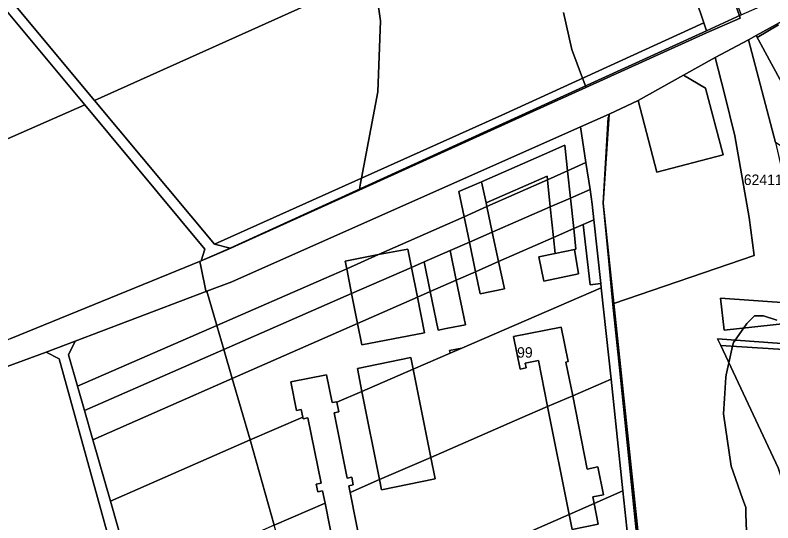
# Model space of a CAD drawing. Extents: x -522079 to -518833, y -1142400 to -1139961.
# Drawn here: x -520985.3 to -520623.1, y -1141048.7 to -1140806 of the extents above; entities that cross this region are included whole.
import ezdxf

# ---------------------------------------------------------------- set-up
doc = ezdxf.new("R2010")
doc.units = 0
for name, color, linetype in [('95560013', 7, 'Continuous'), ('95590013', 7, 'Continuous'), ('95600013', 7, 'Continuous'), ('95610013', 7, 'Continuous'), ('95640013', 7, 'Continuous'), ('95660013', 7, 'Continuous')]:
    doc.layers.add(name, color=color, linetype=linetype)

msp = doc.modelspace()

# ---------------------------------------------------------------- linework, layer by layer
at = {"layer": '95560013'}
for points in [[(-521187.8, -1140573.75), (-521174.07, -1140567.72), (-521175.11, -1140573.76), (-521134.28, -1140622.71), (-521036.95, -1140739.4), (-520947.33, -1140846.85), (-520890.08, -1140915.49), (-520882.47, -1140917.37), (-520896.33, -1140923.45), (-520894.6, -1140917.89), (-520952.05, -1140848.96), (-521041.47, -1140741.65), (-521139.09, -1140624.65), (-521179.71, -1140575.8)], [(-521036.95, -1140739.4), (-520897.82, -1140676.39), (-520765.71, -1140616.57), (-520757.18, -1140627.06), (-520745.42, -1140642.26), (-520733.42, -1140657.97), (-520724.12, -1140671.61), (-520771, -1140692.05), (-520722.34, -1140745.4), (-520809.38, -1140784.65), (-520947.33, -1140846.85)], [(-520752.69, -1140853.85), (-520890.08, -1140915.49), (-520947.33, -1140846.85), (-520809.38, -1140784.65), (-520722.34, -1140745.4), (-520689.02, -1140730.38), (-520682.43, -1140743.84), (-520674.16, -1140762.17), (-520669.15, -1140773.31), (-520664.94, -1140785.33), (-520657.77, -1140804.5), (-520656.02, -1140809.72)], [(-521234.98, -1140825.42), (-521164.66, -1140794.98), (-521041.47, -1140741.65), (-520952.05, -1140848.96), (-521133.42, -1140928.49), (-521179.82, -1140867.68), (-521217.11, -1140828.01)], [(-521133.42, -1140928.49), (-520952.05, -1140848.96), (-520894.6, -1140917.89), (-520896.33, -1140923.45), (-520987.34, -1140960.66), (-521077.97, -1140999.02), (-521081.12, -1140996.97)], [(-520893.74, -1140937.98), (-520888.93, -1140954.41), (-520955.5, -1140983.4), (-520959.78, -1140968.46), (-520956.56, -1140961.79)], [(-520888.93, -1140954.41), (-520885.58, -1140965.84), (-520952.2, -1140994.93), (-520955.5, -1140983.4)], [(-520948.18, -1141008.97), (-520939.75, -1141038.42), (-520928.14, -1141079.25), (-520914.59, -1141129.89), (-520890.98, -1141218.17), (-520890.16, -1141218.54), (-520895.96, -1141221.04), (-520895.4, -1141219.71), (-520927.66, -1141102.94), (-520964.29, -1140970.32), (-520970.5, -1140967.09), (-520956.56, -1140961.79), (-520959.78, -1140968.46), (-520955.5, -1140983.4), (-520952.2, -1140994.93)], [(-520895.4, -1141219.71), (-520895.96, -1141221.04), (-521038.45, -1141284.46), (-521072.62, -1141164.33), (-521112.83, -1141022.98), (-521082.18, -1141009.47), (-521026.59, -1140987.63), (-520970.5, -1140967.09), (-520964.29, -1140970.32), (-520927.66, -1141102.94)], [(-520885.58, -1140965.84), (-520881.52, -1140979.72), (-520948.18, -1141008.97), (-520952.2, -1140994.93)], [(-520881.52, -1140979.72), (-520872.93, -1141009.05), (-520939.75, -1141038.42), (-520948.18, -1141008.97)], [(-520861.45, -1141049.84), (-520928.14, -1141079.25), (-520939.75, -1141038.42), (-520872.93, -1141009.05)]]:
    msp.add_lwpolyline(points, close=True, dxfattribs=at)
at = {"layer": '95590013'}
for points in [[(-520607.5, -1140876.29), (-520621.9, -1140866.86), (-520634.79, -1140817.77), (-520631.12, -1140815.76), (-520626.71, -1140823.74), (-520615.7, -1140843.89), (-520602.23, -1140836.31)], [(-520655.25, -1140840.87), (-520646.86, -1140872.86), (-520678.48, -1140881.15), (-520687.49, -1140846.81), (-520665.74, -1140834.79)], [(-520649.51, -1140960.76), (-520594.75, -1140964.79), (-520599.73, -1140986.18), (-520599.81, -1140983.06), (-520599.94, -1140978.24), (-520600.24, -1140966.98), (-520648.03, -1140963.9)], [(-520620.51, -1141022.34), (-520648.03, -1140963.9), (-520600.24, -1140966.98), (-520604.67, -1140967.12), (-520604.41, -1140978.31), (-520604.3, -1140983.07), (-520599.81, -1140983.06), (-520599.73, -1140986.18), (-520599.09, -1141003), (-520600.97, -1141003.07), (-520601.06, -1141001.34), (-520601.36, -1141001.34), (-520602.52, -1141000.7), (-520603.99, -1141000.76), (-520605.04, -1141001.54), (-520605.37, -1141001.56), (-520605.29, -1141003.25), (-520607.09, -1141003.32), (-520615.08, -1141003.61), (-520614.42, -1141021.92), (-520598.37, -1141020.83), (-520596.21, -1141046.3), (-520612.04, -1141047.58)]]:
    msp.add_lwpolyline(points, close=True, dxfattribs=at)
at = {"layer": '95600013'}
msp.add_lwpolyline([(-520699.09, -1140943.92), (-520704.17, -1140895.93), (-520701.37, -1140853.35), (-520687.49, -1140846.81), (-520678.48, -1140881.15), (-520646.86, -1140872.86), (-520655.25, -1140840.87), (-520665.74, -1140834.79), (-520650.7, -1140826.31), (-520646.19, -1140843.58), (-520641.23, -1140863.72), (-520634.37, -1140902.81), (-520632.04, -1140920.85)], close=True, dxfattribs=at)
at = {"layer": '95610013'}
for points in [[(-520679.92, -1141124.76), (-520699.09, -1140943.92), (-520632.04, -1140920.85), (-520634.37, -1140902.81), (-520641.23, -1140863.72), (-520646.19, -1140843.58), (-520650.7, -1140826.31), (-520634.79, -1140817.77), (-520621.9, -1140866.86), (-520618.56, -1140880.81), (-520614.37, -1140907.34), (-520612.5, -1140933.48), (-520590.36, -1140946.34), (-520594.75, -1140964.79), (-520649.51, -1140960.76), (-520648.03, -1140963.9), (-520620.51, -1141022.34), (-520612.04, -1141047.58), (-520596.21, -1141046.3), (-520599.33, -1141085.41), (-520603.47, -1141094.45), (-520605.48, -1141096), (-520676.95, -1141126.77)], [(-520614.33, -1140943.77), (-520648.15, -1140941.33), (-520646.42, -1140956.53), (-520615.62, -1140953.33)], [(-520615.62, -1140953.33), (-520646.42, -1140956.53), (-520648.15, -1140941.33), (-520614.33, -1140943.77)]]:
    msp.add_lwpolyline(points, close=True, dxfattribs=at)
at = {"layer": '95640013'}
for points in [[(-520657.77, -1140804.5), (-520664.94, -1140785.33), (-520669.15, -1140773.31), (-520674.16, -1140762.17), (-520682.43, -1140743.84), (-520689.02, -1140730.38), (-520701.8, -1140708.2), (-520711.88, -1140691.39), (-520722.11, -1140674.56), (-520715.02, -1140671.04), (-520673.31, -1140722.41), (-520669.12, -1140730.36), (-520666.3, -1140735.71), (-520657.82, -1140755.57), (-520652.69, -1140766.32), (-520641.11, -1140798.37), (-520638.22, -1140805.93), (-520654.73, -1140813.47), (-520656.02, -1140809.72)], [(-520615.7, -1140843.89), (-520626.71, -1140823.74), (-520631.12, -1140815.76), (-520613.67, -1140806.13), (-520609.23, -1140813.72), (-520607.3, -1140817.32), (-520601.28, -1140828.55), (-520598.3, -1140834.1), (-520602.23, -1140836.31)], [(-520654.73, -1140813.47), (-520708.35, -1140837.86), (-520882.47, -1140917.37), (-520890.08, -1140915.49), (-520752.69, -1140853.85), (-520656.02, -1140809.72)], [(-520708.6, -1140903.84), (-520709.39, -1140896.44), (-520710.48, -1140889.38), (-520712.47, -1140876.54), (-520715.12, -1140859.45), (-520701.37, -1140853.35), (-520704.17, -1140895.93), (-520699.09, -1140943.92), (-520679.92, -1141124.76), (-520676.95, -1141126.77), (-520686.99, -1141131.09), (-520684.73, -1141127.15), (-520694.75, -1141033.39), (-520700.46, -1140980.02), (-520705.13, -1140936.35), (-520705.35, -1140934.26)], [(-520893.74, -1140937.98), (-520881.74, -1140933.43), (-520715.12, -1140859.45), (-520712.47, -1140876.54), (-520721.23, -1140880.43), (-520722.52, -1140868.25), (-520732.19, -1140872.47), (-520762.38, -1140885.66), (-520773.2, -1140890.38), (-520770.69, -1140902.38), (-520811.57, -1140920.51), (-520827.55, -1140923.57), (-520826.81, -1140927.27), (-520837.76, -1140932.13), (-520888.93, -1140954.41)], [(-520731.06, -1140883.01), (-520760.22, -1140895.75), (-520762.38, -1140885.66), (-520732.19, -1140872.47), (-520722.52, -1140868.25), (-520721.23, -1140880.43), (-520730.88, -1140884.71)], [(-520712.47, -1140876.54), (-520710.48, -1140889.38), (-520719.85, -1140893.47), (-520721.23, -1140880.43)], [(-520729.49, -1140897.68), (-520730.88, -1140884.71), (-520721.23, -1140880.43), (-520719.85, -1140893.47)], [(-520731.06, -1140883.01), (-520730.88, -1140884.71), (-520759.83, -1140897.56), (-520760.22, -1140895.75)], [(-520759.83, -1140897.56), (-520770.69, -1140902.38), (-520773.2, -1140890.38), (-520762.38, -1140885.66), (-520760.22, -1140895.75)], [(-520730.88, -1140884.71), (-520729.49, -1140897.68), (-520757.2, -1140909.78), (-520759.83, -1140897.56)], [(-520708.6, -1140903.84), (-520713.85, -1140906.14), (-520718.3, -1140908.09), (-520719.85, -1140893.47), (-520710.48, -1140889.38), (-520709.39, -1140896.44)], [(-520718.3, -1140908.09), (-520727.92, -1140912.31), (-520729.49, -1140897.68), (-520719.85, -1140893.47)], [(-520768.14, -1140914.56), (-520770.69, -1140902.38), (-520759.83, -1140897.56), (-520757.2, -1140909.78)], [(-520757.2, -1140909.78), (-520729.49, -1140897.68), (-520727.92, -1140912.31), (-520754.18, -1140923.84)], [(-520789.8, -1140924.02), (-520795.87, -1140926.67), (-520797.62, -1140917.84), (-520811.57, -1140920.51), (-520770.69, -1140902.38), (-520768.14, -1140914.56), (-520777.38, -1140918.59)], [(-520771.7, -1140965.19), (-520777.69, -1140966.37), (-520777.43, -1140967.67), (-520795, -1140975.29), (-520796.11, -1140969.72), (-520821.72, -1140974.86), (-520819.52, -1140985.91), (-520831.48, -1140991.09), (-520831.54, -1140990.79), (-520833.81, -1140991.24), (-520836.46, -1140978.01), (-520853.53, -1140981.34), (-520850.82, -1140994.93), (-520848.51, -1140994.47), (-520847.77, -1140998.15), (-520872.93, -1141009.05), (-520881.52, -1140979.72), (-520821.62, -1140953.44), (-520819.6, -1140963.59), (-520789.67, -1140957.86), (-520793.04, -1140940.9), (-520786.9, -1140938.2), (-520783.12, -1140956.66), (-520778.49, -1140955.67), (-520770.1, -1140954.09), (-520774.48, -1140932.75), (-520765.19, -1140928.67), (-520762.97, -1140939.31), (-520751.37, -1140936.93), (-520754.18, -1140923.84), (-520727.92, -1140912.31), (-520727.11, -1140919.89), (-520735.04, -1140921.52), (-520732.57, -1140933.11), (-520716.01, -1140929.71), (-520717.99, -1140918.02), (-520717.26, -1140917.87), (-520718.3, -1140908.09), (-520713.85, -1140906.14), (-520710.35, -1140934.87), (-520705.35, -1140934.26), (-520705.13, -1140936.35)], [(-520705.35, -1140934.26), (-520710.35, -1140934.87), (-520713.85, -1140906.14), (-520708.6, -1140903.84)], [(-520768.14, -1140914.56), (-520757.2, -1140909.78), (-520754.18, -1140923.84), (-520765.19, -1140928.67)], [(-520718.3, -1140908.09), (-520717.26, -1140917.87), (-520717.99, -1140918.02), (-520727.11, -1140919.89), (-520727.92, -1140912.31)], [(-520765.19, -1140928.67), (-520774.48, -1140932.75), (-520777.38, -1140918.59), (-520768.14, -1140914.56)], [(-520827.55, -1140923.57), (-520811.57, -1140920.51), (-520826.81, -1140927.27)], [(-520826.81, -1140927.27), (-520811.57, -1140920.51), (-520797.62, -1140917.84), (-520795.87, -1140926.67), (-520824.45, -1140939.15)], [(-520777.38, -1140918.59), (-520774.48, -1140932.75), (-520786.9, -1140938.2), (-520789.8, -1140924.02)], [(-520735.04, -1140921.52), (-520727.11, -1140919.89), (-520717.99, -1140918.02), (-520716.01, -1140929.71), (-520732.57, -1140933.11)], [(-520786.9, -1140938.2), (-520793.04, -1140940.9), (-520795.87, -1140926.67), (-520789.8, -1140924.02)], [(-520754.18, -1140923.84), (-520751.37, -1140936.93), (-520762.97, -1140939.31), (-520765.19, -1140928.67)], [(-520837.76, -1140932.13), (-520826.81, -1140927.27), (-520824.45, -1140939.15), (-520885.58, -1140965.84), (-520888.93, -1140954.41)], [(-520793.04, -1140940.9), (-520821.62, -1140953.44), (-520824.45, -1140939.15), (-520795.87, -1140926.67)], [(-520774.48, -1140932.75), (-520770.1, -1140954.09), (-520778.49, -1140955.67), (-520783.12, -1140956.66), (-520786.9, -1140938.2)], [(-520718.75, -1140987.95), (-520721.98, -1140971.84), (-520720.99, -1140971.64), (-520724.28, -1140955.17), (-520747.03, -1140959.63), (-520743.94, -1140975.23), (-520741.04, -1140974.65), (-520741.49, -1140972.39), (-520735.16, -1140971.13), (-520730.77, -1140993.16), (-520743.97, -1140998.9), (-520786.64, -1141017.41), (-520795, -1140975.29), (-520777.43, -1140967.67), (-520771.7, -1140965.19), (-520705.13, -1140936.35), (-520700.46, -1140980.02)], [(-520824.45, -1140939.15), (-520821.62, -1140953.44), (-520881.52, -1140979.72), (-520885.58, -1140965.84)], [(-520789.67, -1140957.86), (-520819.6, -1140963.59), (-520821.62, -1140953.44), (-520793.04, -1140940.9)], [(-520718.75, -1140987.95), (-520730.77, -1140993.16), (-520735.16, -1140971.13), (-520741.49, -1140972.39), (-520741.04, -1140974.65), (-520743.94, -1140975.23), (-520747.03, -1140959.63), (-520724.28, -1140955.17), (-520720.99, -1140971.64), (-520721.98, -1140971.84)], [(-520777.43, -1140967.67), (-520777.69, -1140966.37), (-520771.7, -1140965.19)], [(-520796.11, -1140969.72), (-520795, -1140975.29), (-520819.52, -1140985.91), (-520821.72, -1140974.86)], [(-520811.14, -1141028.03), (-520819.52, -1140985.91), (-520795, -1140975.29), (-520786.64, -1141017.41)], [(-520704.05, -1141035.32), (-520706.71, -1141021.99), (-520711.86, -1141023.01), (-520718.75, -1140987.95), (-520700.46, -1140980.02), (-520694.75, -1141033.39), (-520708.57, -1141039.45), (-520709.19, -1141036.35)], [(-520811.14, -1141028.03), (-520825.24, -1141034.14), (-520825.88, -1141030.94), (-520823.65, -1141030.49), (-520824.37, -1141026.86), (-520826.6, -1141027.31), (-520832.85, -1140996.06), (-520830.61, -1140995.62), (-520831.48, -1140991.09), (-520819.52, -1140985.91)], [(-520704.05, -1141035.32), (-520709.19, -1141036.35), (-520708.57, -1141039.45), (-520720.5, -1141044.69), (-520730.77, -1140993.16), (-520718.75, -1140987.95), (-520711.86, -1141023.01), (-520706.71, -1141021.99)], [(-520847.24, -1141100.33), (-520861.45, -1141049.84), (-520837.18, -1141039.32), (-520830.7, -1141071.68), (-520832.98, -1141072.14), (-520832.28, -1141075.7), (-520829.99, -1141075.25), (-520829.01, -1141080.15), (-520816.54, -1141077.66), (-520825.24, -1141034.14), (-520811.14, -1141028.03), (-520810.16, -1141032.94), (-520784.59, -1141027.7), (-520786.64, -1141017.41), (-520743.97, -1140998.9), (-520730.77, -1140993.16), (-520720.5, -1141044.69)], [(-520847.61, -1140998.97), (-520845.35, -1140998.52), (-520839.1, -1141029.76), (-520841.35, -1141030.21), (-520840.62, -1141033.83), (-520838.37, -1141033.38), (-520837.18, -1141039.32), (-520861.45, -1141049.84), (-520872.93, -1141009.05), (-520847.77, -1140998.15)], [(-520786.64, -1141017.41), (-520784.59, -1141027.7), (-520810.16, -1141032.94), (-520811.14, -1141028.03)], [(-520727.16, -1141148.38), (-520733.88, -1141082.24), (-520846.14, -1141104.23), (-520847.24, -1141100.33), (-520720.5, -1141044.69), (-520719.07, -1141051.88), (-520706.59, -1141049.39), (-520708.57, -1141039.45), (-520694.75, -1141033.39), (-520684.73, -1141127.15), (-520686.99, -1141131.09)], [(-520706.59, -1141049.39), (-520719.07, -1141051.88), (-520720.5, -1141044.69), (-520708.57, -1141039.45)]]:
    msp.add_lwpolyline(points, close=True, dxfattribs=at)
for points in [[(-520987.34, -1140960.66), (-520896.33, -1140923.45), (-520882.47, -1140917.37), (-520708.35, -1140837.86), (-520654.73, -1140813.47), (-520638.22, -1140805.93), (-520618.93, -1140797.21)], [(-520613.67, -1140806.13), (-520631.12, -1140815.76), (-520634.79, -1140817.77), (-520650.7, -1140826.31), (-520665.74, -1140834.79), (-520687.49, -1140846.81), (-520701.37, -1140853.35), (-520715.12, -1140859.45), (-520881.74, -1140933.43), (-520893.74, -1140937.98), (-520956.56, -1140961.79), (-520970.5, -1140967.09), (-521026.59, -1140987.63)], [(-520830.7, -1141071.68), (-520837.18, -1141039.32), (-520838.37, -1141033.38), (-520840.62, -1141033.83), (-520841.35, -1141030.21), (-520839.1, -1141029.76), (-520845.35, -1140998.52), (-520847.61, -1140998.97), (-520847.77, -1140998.15), (-520848.51, -1140994.47), (-520850.82, -1140994.93), (-520853.53, -1140981.34), (-520836.46, -1140978.01), (-520833.81, -1140991.24), (-520831.54, -1140990.79), (-520831.48, -1140991.09), (-520830.61, -1140995.62), (-520832.85, -1140996.06), (-520826.6, -1141027.31), (-520824.37, -1141026.86), (-520823.65, -1141030.49), (-520825.88, -1141030.94), (-520825.24, -1141034.14), (-520816.54, -1141077.66)]]:
    msp.add_lwpolyline(points, dxfattribs=at)
at = {"layer": '95660013'}
for points in [[(-520861.45, -1141049.84), (-520872.93, -1141009.05), (-520881.52, -1140979.72), (-520885.58, -1140965.84), (-520888.93, -1140954.41), (-520893.74, -1140937.98), (-520894.04, -1140938.09), (-520894.13, -1140937.77), (-520896.37, -1140926.81), (-520897, -1140923.72), (-520896.33, -1140923.45), (-520892.32, -1140921.69), (-520883.25, -1140917.88), (-520820.87, -1140889.65), (-520749.39, -1140857.3), (-520732.6, -1140849.71), (-520712.43, -1140840.58), (-520654.77, -1140814.48), (-520638.64, -1140807.47), (-520639.05, -1140806.31), (-520652.97, -1140767)], [(-520652.97, -1140767), (-520639.05, -1140806.31), (-520638.64, -1140807.47), (-520654.77, -1140814.48), (-520712.43, -1140840.58), (-520712.59, -1140840.17), (-520712.71, -1140839.85), (-520714.07, -1140836.22), (-520719.2, -1140822.5), (-520723.13, -1140804.75)], [(-520813.84, -1140786.66), (-520810.7, -1140808.74), (-520811.87, -1140842.73), (-520819.78, -1140883.95), (-520820.24, -1140886.37), (-520820.78, -1140889.2), (-520820.87, -1140889.65), (-520883.25, -1140917.88), (-520892.32, -1140921.69), (-520896.33, -1140923.45), (-520897, -1140923.72), (-520896.37, -1140926.81), (-520894.13, -1140937.77), (-520894.04, -1140938.09), (-520893.74, -1140937.98), (-520888.93, -1140954.41), (-520885.58, -1140965.84), (-520881.52, -1140979.72), (-520872.93, -1141009.05), (-520861.45, -1141049.84)], [(-520723.13, -1140804.75), (-520719.2, -1140822.5), (-520714.07, -1140836.22), (-520712.71, -1140839.85), (-520712.59, -1140840.17), (-520712.43, -1140840.58), (-520732.6, -1140849.71), (-520749.39, -1140857.3), (-520820.87, -1140889.65), (-520820.78, -1140889.2), (-520820.24, -1140886.37), (-520819.78, -1140883.95), (-520811.87, -1140842.73), (-520810.7, -1140808.74), (-520813.84, -1140786.66)], [(-520688.16, -1141055.16), (-520696.42, -1140974.51), (-520699.51, -1140944.36), (-520701.54, -1140923.59), (-520704.24, -1140895.9), (-520701.88, -1140854.99), (-520701.46, -1140854.77), (-520701.37, -1140853.35), (-520687.49, -1140846.81), (-520665.74, -1140834.79), (-520650.7, -1140826.31), (-520634.79, -1140817.77), (-520631.12, -1140815.76), (-520630.61, -1140816.68), (-520620.42, -1140810.73)], [(-520620.42, -1140810.73), (-520630.61, -1140816.68), (-520631.12, -1140815.76), (-520634.79, -1140817.77), (-520650.7, -1140826.31), (-520665.74, -1140834.79), (-520687.49, -1140846.81), (-520701.37, -1140853.35), (-520701.46, -1140854.77), (-520701.88, -1140854.99), (-520704.24, -1140895.9), (-520701.54, -1140923.59), (-520699.51, -1140944.36), (-520696.42, -1140974.51), (-520688.16, -1141055.16)], [(-520621.19, -1140951.83), (-520627.56, -1140949.7), (-520631.81, -1140949.7), (-520635.53, -1140953.43), (-520635.91, -1140953.96), (-520637.03, -1140955.55), (-520641.12, -1140961.37), (-520641.91, -1140962.49), (-520642.3, -1140964.25), (-520644.1, -1140972.24), (-520645.4, -1140978.03), (-520645.62, -1140979.01), (-520646.24, -1140989.25), (-520646.69, -1140996.59), (-520642.97, -1141021.63), (-520637.57, -1141037.05), (-520636.06, -1141041.35), (-520635.95, -1141044.62), (-520635.53, -1141056.8)], [(-520635.53, -1141056.8), (-520635.95, -1141044.62), (-520636.06, -1141041.35), (-520637.57, -1141037.05), (-520642.97, -1141021.63), (-520646.69, -1140996.59), (-520646.24, -1140989.25), (-520645.62, -1140979.01), (-520645.4, -1140978.03), (-520644.1, -1140972.24), (-520642.3, -1140964.25), (-520641.91, -1140962.49), (-520641.12, -1140961.37), (-520637.03, -1140955.55), (-520635.91, -1140953.96), (-520635.53, -1140953.43), (-520631.81, -1140949.7), (-520627.56, -1140949.7), (-520621.19, -1140951.83)]]:
    msp.add_lwpolyline(points, dxfattribs=at)

# ---------------------------------------------------------------- texts
for s, p in [('62411/III.', (-520636.98, -1140887.21)), ('99', (-520745.36, -1140969.76))]:
    msp.add_text(s, height=5, rotation=0, dxfattribs=at).set_placement(p)

doc.saveas('drawing.dxf')
